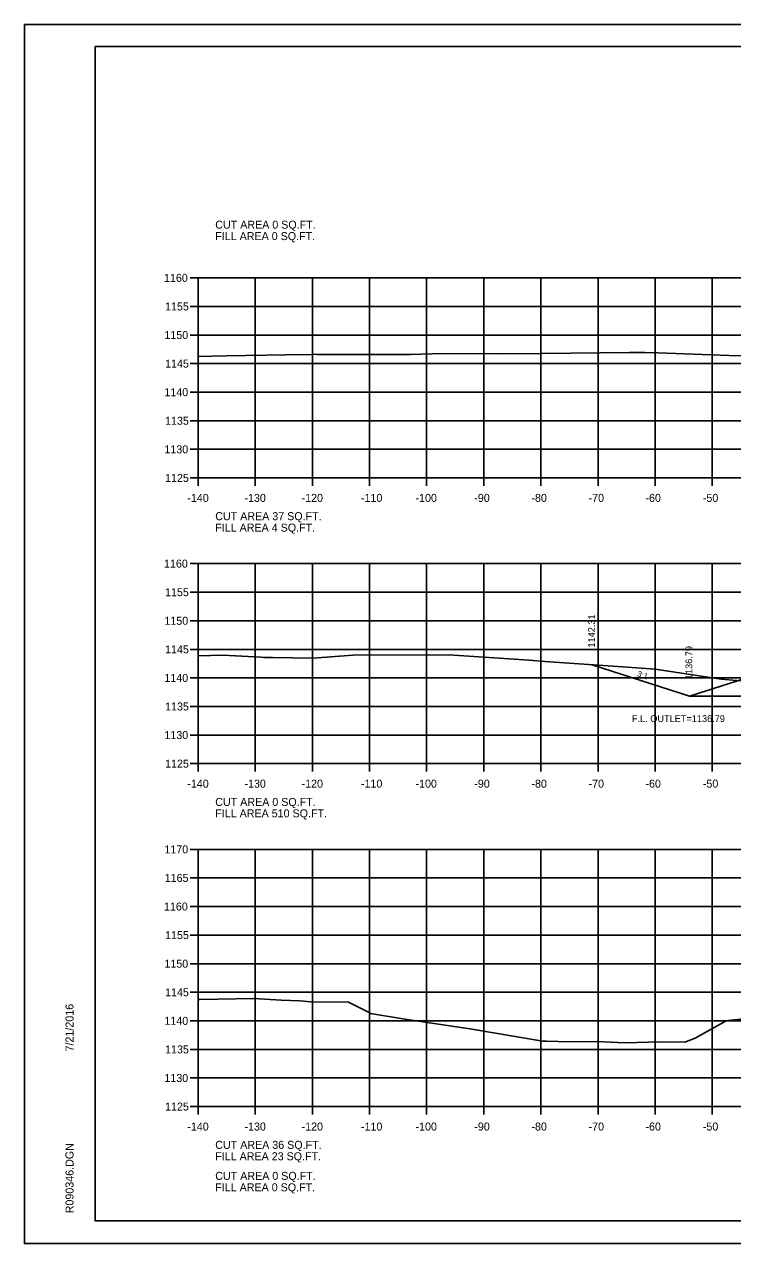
# Model space of a CAD drawing. Extents: x 1368971 to 1374497, y 378717 to 381839.
# Drawn here: x 1368971.2 to 1369095.2, y 381021.5 to 381234.8 of the extents above; entities that cross this region are included whole.
import ezdxf

# ---------------------------------------------------------------- set-up
doc = ezdxf.new("R2010")
doc.units = 0
for name, color, linetype in [('R_Axis', 7, 'Continuous'), ('R_Axis Annot', 7, 'Continuous'), ('R_Border', 7, 'Continuous'), ('R_Exist Surface', 7, 'Continuous'), ('R_Fin Surface', 7, 'Continuous'), ('R_Grid', 7, 'Continuous'), ('R_No Plot', 7, 'Continuous'), ('R_Water', 7, 'Continuous'), ('R_Water Annot', 7, 'Continuous'), ('R_Xsect Elev', 7, 'Continuous'), ('R_Xsect Slope', 7, 'Continuous')]:
    doc.layers.add(name, color=color, linetype=linetype)

msp = doc.modelspace()

# ---------------------------------------------------------------- linework, layer by layer
at = {"layer": 'R_Axis'}
for p, q in [((1369000.2, 381190.44), (1369001.6, 381190.44)), ((1369001.6, 381155.44), (1369001.6, 381190.44)), ((1369000.2, 381185.44), (1369001.6, 381185.44)), ((1369000.2, 381180.44), (1369001.6, 381180.44)), ((1369000.2, 381175.44), (1369001.6, 381175.44)), ((1369000.2, 381170.44), (1369001.6, 381170.44)), ((1369000.2, 381165.44), (1369001.6, 381165.44)), ((1369000.2, 381160.44), (1369001.6, 381160.44)), ((1369000.2, 381155.44), (1369001.6, 381155.44)), ((1369001.6, 381155.44), (1369281.6, 381155.44)), ((1369001.6, 381154.04), (1369001.6, 381155.44)), ((1369011.6, 381154.04), (1369011.6, 381155.44)), ((1369021.6, 381154.04), (1369021.6, 381155.44)), ((1369031.6, 381154.04), (1369031.6, 381155.44)), ((1369041.6, 381154.04), (1369041.6, 381155.44)), ((1369051.6, 381154.04), (1369051.6, 381155.44)), ((1369061.6, 381154.04), (1369061.6, 381155.44)), ((1369071.6, 381154.04), (1369071.6, 381155.44)), ((1369081.6, 381154.04), (1369081.6, 381155.44)), ((1369091.6, 381154.04), (1369091.6, 381155.44)), ((1369000.2, 381140.44), (1369001.6, 381140.44)), ((1369001.6, 381105.44), (1369001.6, 381140.44)), ((1369000.2, 381135.44), (1369001.6, 381135.44)), ((1369000.2, 381130.44), (1369001.6, 381130.44)), ((1369000.2, 381125.44), (1369001.6, 381125.44)), ((1369000.2, 381120.44), (1369001.6, 381120.44)), ((1369000.2, 381115.44), (1369001.6, 381115.44)), ((1369000.2, 381110.44), (1369001.6, 381110.44)), ((1369000.2, 381105.44), (1369001.6, 381105.44)), ((1369001.6, 381105.44), (1369281.6, 381105.44)), ((1369001.6, 381104.04), (1369001.6, 381105.44)), ((1369011.6, 381104.04), (1369011.6, 381105.44)), ((1369021.6, 381104.04), (1369021.6, 381105.44)), ((1369031.6, 381104.04), (1369031.6, 381105.44)), ((1369041.6, 381104.04), (1369041.6, 381105.44)), ((1369051.6, 381104.04), (1369051.6, 381105.44)), ((1369061.6, 381104.04), (1369061.6, 381105.44)), ((1369071.6, 381104.04), (1369071.6, 381105.44)), ((1369081.6, 381104.04), (1369081.6, 381105.44)), ((1369091.6, 381104.04), (1369091.6, 381105.44)), ((1369000.2, 381090.44), (1369001.6, 381090.44)), ((1369001.6, 381045.44), (1369001.6, 381090.44)), ((1369000.2, 381085.44), (1369001.6, 381085.44)), ((1369000.2, 381080.44), (1369001.6, 381080.44)), ((1369000.2, 381075.44), (1369001.6, 381075.44)), ((1369000.2, 381070.44), (1369001.6, 381070.44)), ((1369000.2, 381065.44), (1369001.6, 381065.44)), ((1369000.2, 381060.44), (1369001.6, 381060.44)), ((1369000.2, 381055.44), (1369001.6, 381055.44)), ((1369000.2, 381050.44), (1369001.6, 381050.44)), ((1369000.2, 381045.44), (1369001.6, 381045.44)), ((1369001.6, 381045.44), (1369281.6, 381045.44)), ((1369001.6, 381044.04), (1369001.6, 381045.44)), ((1369011.6, 381044.04), (1369011.6, 381045.44)), ((1369021.6, 381044.04), (1369021.6, 381045.44)), ((1369031.6, 381044.04), (1369031.6, 381045.44)), ((1369041.6, 381044.04), (1369041.6, 381045.44)), ((1369051.6, 381044.04), (1369051.6, 381045.44)), ((1369061.6, 381044.04), (1369061.6, 381045.44)), ((1369071.6, 381044.04), (1369071.6, 381045.44)), ((1369081.6, 381044.04), (1369081.6, 381045.44)), ((1369091.6, 381044.04), (1369091.6, 381045.44))]:
    msp.add_line(p, q, dxfattribs=at)
at = {"layer": 'R_Border'}
for p, q in [((1368983.6, 381230.9), (1369299.78, 381230.9)), ((1368983.6, 381025.44), (1368983.6, 381230.9)), ((1368983.6, 381025.44), (1368983.6, 381025.44)), ((1369299.78, 381025.44), (1368983.6, 381025.44))]:
    msp.add_line(p, q, dxfattribs=at)
at = {"layer": 'R_Exist Surface'}
for points in [[(1369001.6, 381176.68), (1369006.48, 381176.79), (1369016.92, 381176.98), (1369021.72, 381177.05), (1369022.14, 381177.07), (1369022.37, 381177.06), (1369023.17, 381177.06), (1369038.76, 381177.06), (1369044.41, 381177.19), (1369054.52, 381177.14), (1369061.69, 381177.18), (1369077.08, 381177.36), (1369079.08, 381177.39), (1369079.71, 381177.4), (1369082.04, 381177.31), (1369094.55, 381176.88), (1369100.87, 381176.7)], [(1369001.6, 381124.32), (1369005.9, 381124.41), (1369012.55, 381124.07), (1369013.24, 381124.04), (1369013.51, 381124.04), (1369014.63, 381124.01), (1369021.76, 381123.87), (1369028.68, 381124.42), (1369041.94, 381124.47), (1369042.89, 381124.45), (1369045.5, 381124.48), (1369059.54, 381123.53), (1369062.26, 381123.32), (1369075.09, 381122.43), (1369081.61, 381121.97), (1369093.15, 381120.25), (1369098.65, 381119.76)], [(1369001.6, 381064.13), (1369001.67, 381064.18), (1369001.91, 381064.18), (1369011.34, 381064.34), (1369016.14, 381064.08), (1369019.4, 381063.91), (1369021.34, 381063.79), (1369027.93, 381063.68), (1369031.55, 381061.89), (1369031.76, 381061.73), (1369037.45, 381060.81), (1369049.16, 381059.01), (1369061.92, 381056.88), (1369062.6, 381056.89), (1369064.6, 381056.85), (1369072.58, 381056.75), (1369076.25, 381056.61), (1369082.65, 381056.75), (1369086.78, 381056.7), (1369088.6, 381057.42), (1369094.04, 381060.43), (1369094.31, 381060.48), (1369096.62, 381060.73)]]:
    msp.add_lwpolyline(points, dxfattribs=at)
at = {"layer": 'R_Fin Surface'}
for p, q in [((1369113.64, 381125.57), (1369087.6, 381117.23)), ((1369087.6, 381117.23), (1369070.57, 381122.75))]:
    msp.add_line(p, q, dxfattribs=at)
at = {"layer": 'R_Grid'}
for p, q in [((1369001.6, 381190.44), (1369281.6, 381190.44)), ((1369001.6, 381155.44), (1369001.6, 381190.44)), ((1369011.6, 381155.44), (1369011.6, 381190.44)), ((1369021.6, 381155.44), (1369021.6, 381190.44)), ((1369031.6, 381155.44), (1369031.6, 381190.44)), ((1369041.6, 381155.44), (1369041.6, 381190.44)), ((1369051.6, 381155.44), (1369051.6, 381190.44)), ((1369061.6, 381155.44), (1369061.6, 381190.44)), ((1369071.6, 381155.44), (1369071.6, 381190.44)), ((1369081.6, 381155.44), (1369081.6, 381190.44)), ((1369091.6, 381155.44), (1369091.6, 381190.44)), ((1369001.6, 381185.44), (1369281.6, 381185.44)), ((1369001.6, 381180.44), (1369281.6, 381180.44)), ((1369001.6, 381175.44), (1369281.6, 381175.44)), ((1369001.6, 381170.44), (1369281.6, 381170.44)), ((1369001.6, 381165.44), (1369281.6, 381165.44)), ((1369001.6, 381160.44), (1369281.6, 381160.44)), ((1369001.6, 381155.44), (1369281.6, 381155.44)), ((1369001.6, 381140.44), (1369281.6, 381140.44)), ((1369001.6, 381105.44), (1369001.6, 381140.44)), ((1369011.6, 381105.44), (1369011.6, 381140.44)), ((1369021.6, 381105.44), (1369021.6, 381140.44)), ((1369031.6, 381105.44), (1369031.6, 381140.44)), ((1369041.6, 381105.44), (1369041.6, 381140.44)), ((1369051.6, 381105.44), (1369051.6, 381140.44)), ((1369061.6, 381105.44), (1369061.6, 381140.44)), ((1369071.6, 381105.44), (1369071.6, 381140.44)), ((1369081.6, 381105.44), (1369081.6, 381140.44)), ((1369091.6, 381105.44), (1369091.6, 381140.44)), ((1369001.6, 381135.44), (1369281.6, 381135.44)), ((1369001.6, 381130.44), (1369281.6, 381130.44)), ((1369001.6, 381125.44), (1369281.6, 381125.44)), ((1369001.6, 381120.44), (1369281.6, 381120.44)), ((1369001.6, 381115.44), (1369281.6, 381115.44)), ((1369001.6, 381110.44), (1369281.6, 381110.44)), ((1369001.6, 381105.44), (1369281.6, 381105.44)), ((1369001.6, 381090.44), (1369281.6, 381090.44)), ((1369001.6, 381045.44), (1369001.6, 381090.44)), ((1369011.6, 381045.44), (1369011.6, 381090.44)), ((1369021.6, 381045.44), (1369021.6, 381090.44)), ((1369031.6, 381045.44), (1369031.6, 381090.44)), ((1369041.6, 381045.44), (1369041.6, 381090.44)), ((1369051.6, 381045.44), (1369051.6, 381090.44)), ((1369061.6, 381045.44), (1369061.6, 381090.44)), ((1369071.6, 381045.44), (1369071.6, 381090.44)), ((1369081.6, 381045.44), (1369081.6, 381090.44)), ((1369091.6, 381045.44), (1369091.6, 381090.44)), ((1369001.6, 381085.44), (1369281.6, 381085.44)), ((1369001.6, 381080.44), (1369281.6, 381080.44)), ((1369001.6, 381075.44), (1369281.6, 381075.44)), ((1369001.6, 381070.44), (1369281.6, 381070.44)), ((1369001.6, 381065.44), (1369281.6, 381065.44)), ((1369001.6, 381060.44), (1369281.6, 381060.44)), ((1369001.6, 381055.44), (1369281.6, 381055.44)), ((1369001.6, 381050.44), (1369281.6, 381050.44)), ((1369001.6, 381045.44), (1369281.6, 381045.44))]:
    msp.add_line(p, q, dxfattribs=at)
at = {"layer": 'R_No Plot'}
for p, q in [((1368971.2, 381234.79), (1369304.53, 381234.79)), ((1368971.2, 381021.46), (1369304.53, 381021.46))]:
    msp.add_line(p, q, dxfattribs=at)
for points in [[(1368971.19, 381234.79), (1369304.53, 381234.79), (1369304.53, 381021.46), (1368971.19, 381021.46)], [(1369217.52, 381230.9), (1369217.52, 381221.02), (1369253.25, 381221.02), (1369253.25, 381218.1), (1369276.45, 381218.1), (1369276.45, 381194.89), (1369299.78, 381194.89), (1369299.78, 381025.44), (1368983.6, 381025.44), (1368983.6, 381230.9)]]:
    msp.add_lwpolyline(points, close=True, dxfattribs=at)
at = {"layer": 'R_Water'}
msp.add_line((1369111.61, 381117.28), (1369087.6, 381117.23), dxfattribs=at)

# ---------------------------------------------------------------- texts
at = {"layer": 'R_Axis'}
for p in [(1369001.6, 381155.44), (1369001.6, 381105.44), (1369001.6, 381045.44)]:
    msp.add_text('-', height=0.0001, dxfattribs=at).set_placement(p)
at = {"layer": 'R_Axis Annot'}
for s, p in [('CUT AREA 0 SQ.FT.', (1369004.6, 381199.05)), ('FILL AREA 0 SQ.FT.', (1369004.6, 381197.05)), ('1160', (1368995.63, 381189.74)), ('1155', (1368995.82, 381184.74)), ('1150', (1368995.7, 381179.74)), ('1145', (1368995.82, 381174.74)), ('1140', (1368995.7, 381169.74)), ('1135', (1368995.82, 381164.74)), ('1130', (1368995.7, 381159.74)), ('1125', (1368995.82, 381154.74)), ('-140', (1368999.71, 381151.24)), ('-130', (1369009.71, 381151.24)), ('-120', (1369019.71, 381151.24)), ('-110', (1369030.1, 381151.24)), ('-100', (1369039.65, 381151.24)), ('-90', (1369049.94, 381151.24)), ('-80', (1369059.94, 381151.24)), ('-70', (1369069.94, 381151.24)), ('-60', (1369079.9, 381151.24)), ('-50', (1369089.94, 381151.24)), ('CUT AREA 37 SQ.FT.', (1369004.6, 381148.04)), ('FILL AREA 4 SQ.FT.', (1369004.6, 381146.04)), ('1160', (1368995.63, 381139.74)), ('1155', (1368995.82, 381134.74)), ('1150', (1368995.7, 381129.74)), ('1145', (1368995.82, 381124.74)), ('1140', (1368995.7, 381119.74)), ('1135', (1368995.82, 381114.74)), ('1130', (1368995.7, 381109.74)), ('1125', (1368995.82, 381104.74)), ('-140', (1368999.71, 381101.24)), ('-130', (1369009.71, 381101.24)), ('-120', (1369019.71, 381101.24)), ('-110', (1369030.1, 381101.24)), ('-100', (1369039.65, 381101.24)), ('-90', (1369049.94, 381101.24)), ('-80', (1369059.94, 381101.24)), ('-70', (1369069.94, 381101.24)), ('-60', (1369079.9, 381101.24)), ('-50', (1369089.94, 381101.24)), ('CUT AREA 0 SQ.FT.', (1369004.6, 381098.04)), ('FILL AREA 510 SQ.FT.', (1369004.6, 381096.04)), ('1170', (1368995.7, 381089.74)), ('1165', (1368995.75, 381084.74)), ('1160', (1368995.63, 381079.74)), ('1155', (1368995.82, 381074.74)), ('1150', (1368995.7, 381069.74)), ('1145', (1368995.82, 381064.74)), ('1140', (1368995.7, 381059.74)), ('1135', (1368995.82, 381054.74)), ('1130', (1368995.7, 381049.74)), ('1125', (1368995.82, 381044.74)), ('-140', (1368999.71, 381041.24)), ('-130', (1369009.71, 381041.24)), ('-120', (1369019.71, 381041.24)), ('-110', (1369030.1, 381041.24)), ('-100', (1369039.65, 381041.24)), ('-90', (1369049.94, 381041.24)), ('-80', (1369059.94, 381041.24)), ('-70', (1369069.94, 381041.24)), ('-60', (1369079.9, 381041.24)), ('-50', (1369089.94, 381041.24)), ('CUT AREA 36 SQ.FT.', (1369004.6, 381038.04)), ('FILL AREA 23 SQ.FT.', (1369004.6, 381036.04)), ('CUT AREA 0 SQ.FT.', (1369004.6, 381032.61)), ('FILL AREA 0 SQ.FT.', (1369004.6, 381030.61))]:
    msp.add_text(s, height=1.4, dxfattribs=at).set_placement(p)
at = {"layer": 'R_Border'}
for s, p in [('7/21/2016', (1368979.79, 381055.08)), ('R090346.DGN', (1368979.79, 381026.76))]:
    msp.add_text(s, height=1.4, rotation=90, dxfattribs=at).set_placement(p)
at = {"layer": 'R_Water Annot'}
msp.add_text('F.L. OUTLET=1136.79', height=1.2, dxfattribs=at).set_placement((1369077.53, 381112.72))
at = {"layer": 'R_Xsect Elev'}
for s, p in [('1142.31', (1369071.07, 381125.75)), ('1136.79', (1369088.1, 381120.23))]:
    msp.add_text(s, height=1.2, rotation=90, dxfattribs=at).set_placement(p)
at = {"layer": 'R_Xsect Slope'}
msp.add_text('3:1', height=1, rotation=342.0537, dxfattribs=at).set_placement((1369078.37, 381120.74))

doc.saveas('drawing.dxf')
